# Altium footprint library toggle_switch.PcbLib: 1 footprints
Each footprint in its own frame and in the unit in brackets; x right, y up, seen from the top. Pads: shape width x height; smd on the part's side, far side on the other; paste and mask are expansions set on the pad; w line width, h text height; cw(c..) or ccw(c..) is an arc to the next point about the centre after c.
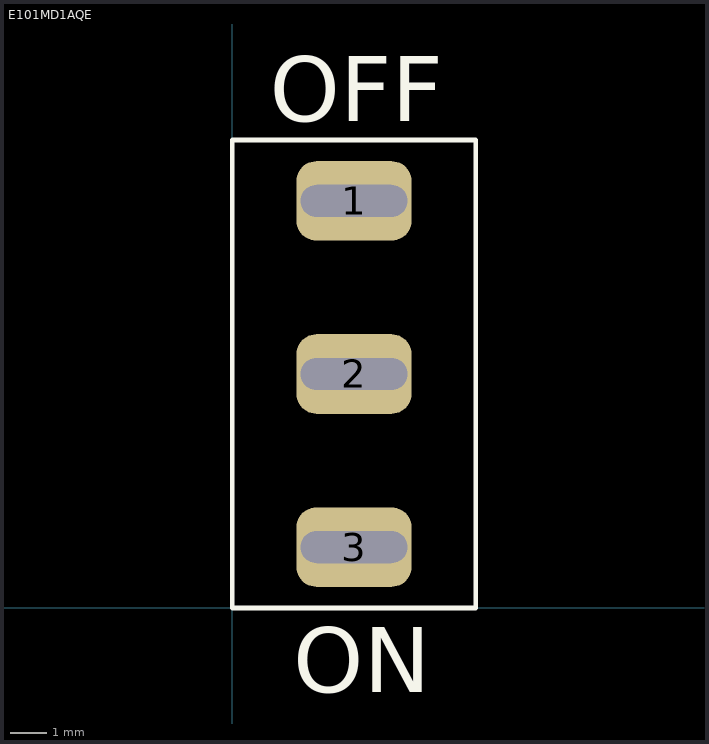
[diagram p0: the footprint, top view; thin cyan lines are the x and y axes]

## E101MD1AQE [mil] "SWITCH TOGGLE SPDT 7.5A 125V"
pads (3):
  rrect50% 123x85 hole 34 slot 114 at 0 deg: 1(130,435) 2(130,250) 3(130,65)
Top Overlay:
  lines w5: 0,0 260,0 260,500 0,500 0,0
  text "OFF" at 40,520 h70
  text "ON" at 65,-90 h70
